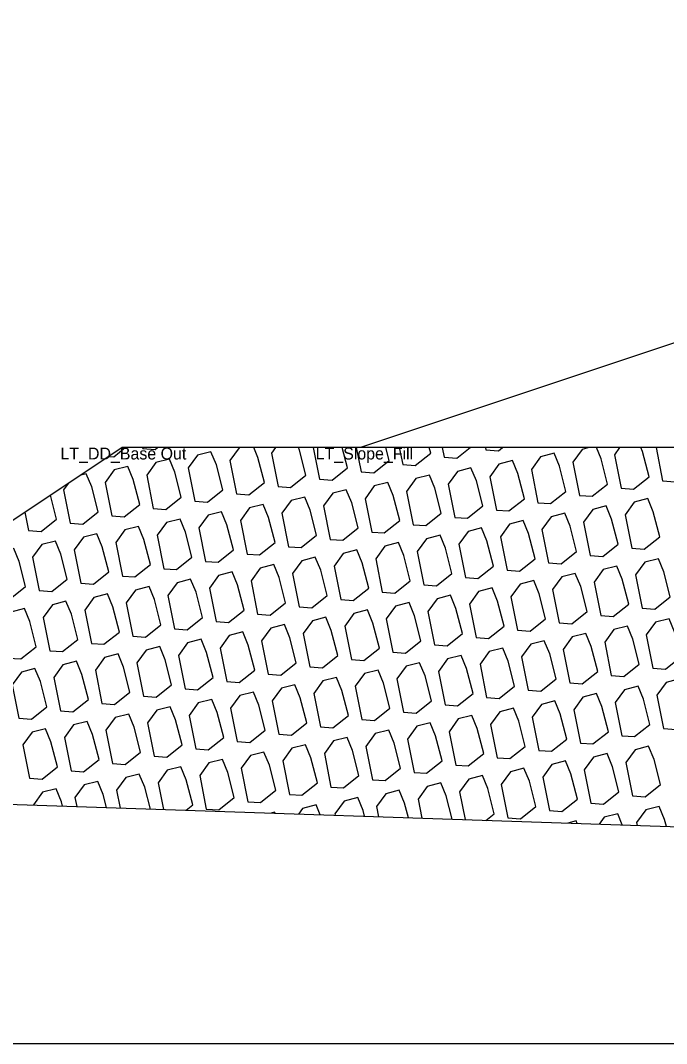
# Model space of a CAD drawing. Extents: x -26 to 203, y -10 to 20020.
# Drawn here: x 66.4 to 71.82, y 16000 to 16008.58 of the extents above; entities that cross this region are included whole.
import ezdxf

# ---------------------------------------------------------------- set-up
doc = ezdxf.new("R2010")
doc.units = 0
for name, color, linetype in [('Default', 7, 'Continuous'), ('Exist Cross Section Cell', 7, 'Continuous'), ('Exist XS Ground Line', 7, 'Continuous'), ('Old_Level_1', 7, 'Continuous'), ('Prop CMT Rip Rap Class II', 7, 'Continuous'), ('Prop CMT Slope Grass', 7, 'Continuous')]:
    doc.layers.add(name, color=color, linetype=linetype)

msp = doc.modelspace()

# ---------------------------------------------------------------- linework, layer by layer
at = {"layer": 'Exist Cross Section Cell'}
msp.add_line((0, 16000), (100, 16000), dxfattribs=at)
at = {"layer": 'Exist XS Ground Line'}
msp.add_line((50.1607, 16002.5529), (73.7016, 16001.7575), dxfattribs=at)
at = {"layer": 'Old_Level_1'}
for p, q in [((67.4213, 16005), (67.4229, 16004.992)), ((68.8532, 16005), (68.9061, 16004.7338)), ((69.2141, 16005), (69.2547, 16004.7952)), ((69.5749, 16005), (69.6033, 16004.8567)), ((69.9357, 16005), (69.9519, 16004.9182)), ((70.2965, 16005), (70.3005, 16004.9796)), ((71.7285, 16005), (71.7838, 16004.7214)), ((66.4354, 16004.4571), (66.4659, 16004.3035))]:
    msp.add_line(p, q, dxfattribs=at)
for points in [[(67.1385, 16004.9258), (67.1795, 16004.9228), (67.2764, 16005)], [(67.4229, 16004.992), (67.5281, 16004.9843), (67.5478, 16005)], [(68.241, 16005), (68.2304, 16004.9972), (68.1533, 16004.8908), (68.2089, 16004.6108)], [(68.2089, 16004.6108), (68.3142, 16004.6032), (68.4437, 16004.7064), (68.3893, 16004.917), (68.3551, 16005)], [(68.5365, 16005), (68.5019, 16004.9523), (68.5575, 16004.6723)], [(68.5575, 16004.6723), (68.6628, 16004.6646), (68.7923, 16004.7679), (68.7379, 16004.9784), (68.729, 16005)], [(68.9061, 16004.7338), (69.0114, 16004.7261), (69.1409, 16004.8293), (69.0968, 16005)], [(69.2547, 16004.7952), (69.36, 16004.7876), (69.4895, 16004.8908), (69.4613, 16005)], [(69.6033, 16004.8567), (69.7086, 16004.849), (69.8381, 16004.9523), (69.8258, 16005)], [(69.9519, 16004.9182), (70.0572, 16004.9105), (70.1695, 16005)], [(70.3005, 16004.9796), (70.4058, 16004.972), (70.4409, 16005)], [(71.1664, 16005), (71.108, 16004.9849), (71.031, 16004.8785), (71.0866, 16004.5985)], [(71.0866, 16004.5985), (71.1918, 16004.5908), (71.3214, 16004.6941), (71.2669, 16004.9046), (71.2277, 16005)], [(71.4231, 16005), (71.3796, 16004.94), (71.4352, 16004.66)], [(71.4352, 16004.66), (71.5404, 16004.6523), (71.67, 16004.7555), (71.6155, 16004.9661), (71.6016, 16005)], [(71.7838, 16004.7214), (71.889, 16004.7138), (72.0186, 16004.817), (71.9713, 16005)], [(66.8145, 16004.365), (66.9198, 16004.3573), (67.0493, 16004.4605), (66.9949, 16004.6711), (66.9498, 16004.7808), (66.9027, 16004.7686)], [(66.7979, 16004.6988), (66.7589, 16004.6449), (66.8145, 16004.365)], [(66.4659, 16004.3035), (66.5712, 16004.2958), (66.7008, 16004.3991), (66.6489, 16004.5995)], [(67.7867, 16001.9573), (67.8423, 16002.0016), (67.7879, 16002.2122), (67.7428, 16002.3219), (67.629, 16002.2925), (67.5519, 16002.1861), (67.5961, 16001.9638)], [(67.119, 16001.9799), (67.0907, 16002.0893), (67.0456, 16002.199), (66.9318, 16002.1696), (66.8547, 16002.0631), (66.8696, 16001.9883)], [(67.4867, 16001.9675), (67.4393, 16002.1508), (67.3942, 16002.2604), (67.2804, 16002.231), (67.2033, 16002.1246), (67.2328, 16001.976)], [(70.0188, 16001.8819), (69.9684, 16002.077), (69.9232, 16002.1866), (69.8095, 16002.1572), (69.7324, 16002.0508), (69.7642, 16001.8905)], [(70.3018, 16001.8724), (70.3714, 16001.9278), (70.317, 16002.1384), (70.2718, 16002.2481), (70.1581, 16002.2187), (70.081, 16002.1123), (70.1275, 16001.8782)], [(66.7513, 16001.9923), (66.7421, 16002.0278), (66.697, 16002.1375), (66.5832, 16002.1081), (66.5061, 16002.0017), (66.5064, 16002.0006)], [(69.6511, 16001.8943), (69.6198, 16002.0155), (69.5746, 16002.1252), (69.4609, 16002.0958), (69.3838, 16001.9893), (69.401, 16001.9028)], [(69.2834, 16001.9068), (69.2712, 16001.954), (69.226, 16002.0637), (69.1123, 16002.0343), (69.0352, 16001.9279), (69.0377, 16001.9151)], [(68.5324, 16001.9321), (68.5288, 16001.9408), (68.4997, 16001.9332)], [(68.9116, 16001.9193), (68.8774, 16002.0022), (68.7637, 16001.9728), (68.7294, 16001.9255)], [(71.4455, 16001.8337), (71.4065, 16001.9284), (71.2927, 16001.899), (71.2502, 16001.8403)], [(71.8155, 16001.8212), (71.8002, 16001.8802), (71.7551, 16001.9899), (71.6413, 16001.9605), (71.5643, 16001.8541), (71.5691, 16001.8295)], [(71.0663, 16001.8465), (71.0579, 16001.867), (70.9889, 16001.8491)]]:
    msp.add_lwpolyline(points, dxfattribs=at)
for points in [[(67.8603, 16004.5494), (67.9656, 16004.5417), (68.0951, 16004.6449), (68.0407, 16004.8555), (67.9955, 16004.9652), (67.8818, 16004.9358), (67.8047, 16004.8294)], [(70.738, 16004.537), (70.8433, 16004.5294), (70.9728, 16004.6326), (70.9183, 16004.8432), (70.8732, 16004.9529), (70.7594, 16004.9234), (70.6824, 16004.817)], [(67.1631, 16004.4264), (67.2684, 16004.4188), (67.3979, 16004.522), (67.3435, 16004.7326), (67.2984, 16004.8423), (67.1846, 16004.8128), (67.1075, 16004.7064)], [(67.5117, 16004.4879), (67.617, 16004.4802), (67.7465, 16004.5835), (67.6921, 16004.794), (67.647, 16004.9037), (67.5332, 16004.8743), (67.4561, 16004.7679)], [(70.3894, 16004.4756), (70.4947, 16004.4679), (70.6242, 16004.5711), (70.5697, 16004.7817), (70.5246, 16004.8914), (70.4108, 16004.862), (70.3338, 16004.7556)], [(69.6922, 16004.3526), (69.7975, 16004.345), (69.927, 16004.4482), (69.8726, 16004.6588), (69.8274, 16004.7685), (69.7137, 16004.739), (69.6366, 16004.6326)], [(70.0408, 16004.4141), (70.1461, 16004.4064), (70.2756, 16004.5097), (70.2212, 16004.7202), (70.176, 16004.8299), (70.0622, 16004.8005), (69.9852, 16004.6941)], [(69.3436, 16004.2912), (69.4489, 16004.2835), (69.5784, 16004.3867), (69.524, 16004.5973), (69.4788, 16004.707), (69.3651, 16004.6776), (69.288, 16004.5712)], [(68.6464, 16004.1682), (68.7517, 16004.1606), (68.8812, 16004.2638), (68.8268, 16004.4744), (68.7816, 16004.5841), (68.6679, 16004.5546), (68.5908, 16004.4482)], [(68.995, 16004.2297), (69.1003, 16004.222), (69.2298, 16004.3253), (69.1754, 16004.5358), (69.1302, 16004.6455), (69.0165, 16004.6161), (68.9394, 16004.5097)], [(68.2978, 16004.1068), (68.4031, 16004.0991), (68.5326, 16004.2023), (68.4782, 16004.4129), (68.433, 16004.5226), (68.3193, 16004.4932), (68.2422, 16004.3867)], [(71.1755, 16004.0944), (71.2807, 16004.0868), (71.4103, 16004.19), (71.3558, 16004.4006), (71.3107, 16004.5103), (71.1969, 16004.4808), (71.1199, 16004.3744)], [(71.5241, 16004.1559), (71.6293, 16004.1482), (71.7589, 16004.2515), (71.7044, 16004.462), (71.6593, 16004.5717), (71.5455, 16004.5423), (71.4685, 16004.4359)], [(67.9492, 16004.0453), (68.0545, 16004.0376), (68.184, 16004.1409), (68.1296, 16004.3514), (68.0844, 16004.4611), (67.9707, 16004.4317), (67.8936, 16004.3253)], [(70.8269, 16004.033), (70.9321, 16004.0253), (71.0617, 16004.1285), (71.0072, 16004.3391), (70.9621, 16004.4488), (70.8483, 16004.4194), (70.7713, 16004.3129)], [(67.252, 16003.9224), (67.3573, 16003.9147), (67.4868, 16004.0179), (67.4324, 16004.2285), (67.3872, 16004.3382), (67.2735, 16004.3088), (67.1964, 16004.2023)], [(67.6006, 16003.9838), (67.7059, 16003.9762), (67.8354, 16004.0794), (67.781, 16004.29), (67.7358, 16004.3997), (67.6221, 16004.3702), (67.545, 16004.2638)], [(70.1297, 16003.91), (70.2349, 16003.9024), (70.3645, 16004.0056), (70.31, 16004.2162), (70.2649, 16004.3259), (70.1511, 16004.2964), (70.0741, 16004.19)], [(70.4783, 16003.9715), (70.5835, 16003.9638), (70.7131, 16004.0671), (70.6586, 16004.2776), (70.6135, 16004.3873), (70.4997, 16004.3579), (70.4227, 16004.2515)], [(66.9034, 16003.8609), (67.0087, 16003.8532), (67.1382, 16003.9565), (67.0838, 16004.167), (67.0386, 16004.2767), (66.9249, 16004.2473), (66.8478, 16004.1409)], [(69.7811, 16003.8486), (69.8863, 16003.8409), (70.0159, 16003.9441), (69.9614, 16004.1547), (69.9163, 16004.2644), (69.8025, 16004.235), (69.7255, 16004.1285)], [(66.2062, 16003.738), (66.3115, 16003.7303), (66.441, 16003.8335), (66.3866, 16004.0441), (66.3414, 16004.1538), (66.2277, 16004.1244), (66.1506, 16004.0179)], [(66.5548, 16003.7994), (66.6601, 16003.7918), (66.7896, 16003.895), (66.7352, 16004.1056), (66.69, 16004.2153), (66.5763, 16004.1858), (66.4992, 16004.0794)], [(69.4325, 16003.7871), (69.5377, 16003.7794), (69.6673, 16003.8827), (69.6128, 16004.0932), (69.5677, 16004.2029), (69.4539, 16004.1735), (69.3769, 16004.0671)], [(68.7353, 16003.6642), (68.8406, 16003.6565), (68.9701, 16003.7597), (68.9156, 16003.9703), (68.8705, 16004.08), (68.7567, 16004.0506), (68.6797, 16003.9441)], [(69.0839, 16003.7256), (69.1892, 16003.718), (69.3187, 16003.8212), (69.2642, 16004.0318), (69.2191, 16004.1415), (69.1053, 16004.112), (69.0283, 16004.0056)], [(71.6129, 16003.6518), (71.7182, 16003.6442), (71.8477, 16003.7474), (71.7933, 16003.958), (71.7482, 16004.0677), (71.6344, 16004.0382), (71.5573, 16003.9318)], [(68.3867, 16003.6027), (68.492, 16003.595), (68.6215, 16003.6983), (68.5671, 16003.9088), (68.5219, 16004.0185), (68.4081, 16003.9891), (68.3311, 16003.8827)], [(71.2643, 16003.5904), (71.3696, 16003.5827), (71.4991, 16003.6859), (71.4447, 16003.8965), (71.3996, 16004.0062), (71.2858, 16003.9768), (71.2087, 16003.8703)], [(67.6895, 16003.4798), (67.7948, 16003.4721), (67.9243, 16003.5753), (67.8699, 16003.7859), (67.8247, 16003.8956), (67.711, 16003.8662), (67.6339, 16003.7597)], [(68.0381, 16003.5412), (68.1434, 16003.5336), (68.2729, 16003.6368), (68.2185, 16003.8474), (68.1733, 16003.9571), (68.0595, 16003.9276), (67.9825, 16003.8212)], [(70.9158, 16003.5289), (71.021, 16003.5212), (71.1506, 16003.6245), (71.0961, 16003.835), (71.051, 16003.9447), (70.9372, 16003.9153), (70.8601, 16003.8089)], [(67.3409, 16003.4183), (67.4462, 16003.4106), (67.5757, 16003.5139), (67.5213, 16003.7244), (67.4761, 16003.8341), (67.3624, 16003.8047), (67.2853, 16003.6983)], [(70.2186, 16003.406), (70.3238, 16003.3983), (70.4534, 16003.5015), (70.3989, 16003.7121), (70.3538, 16003.8218), (70.24, 16003.7924), (70.1629, 16003.6859)], [(70.5672, 16003.4674), (70.6724, 16003.4598), (70.802, 16003.563), (70.7475, 16003.7736), (70.7024, 16003.8833), (70.5886, 16003.8538), (70.5115, 16003.7474)], [(66.9923, 16003.3568), (67.0976, 16003.3492), (67.2271, 16003.4524), (67.1727, 16003.663), (67.1275, 16003.7727), (67.0138, 16003.7432), (66.9367, 16003.6368)], [(69.87, 16003.3445), (69.9752, 16003.3368), (70.1048, 16003.4401), (70.0503, 16003.6506), (70.0052, 16003.7603), (69.8914, 16003.7309), (69.8144, 16003.6245)], [(66.2951, 16003.2339), (66.4004, 16003.2262), (66.5299, 16003.3295), (66.4755, 16003.54), (66.4303, 16003.6497), (66.3166, 16003.6203), (66.2395, 16003.5139)], [(66.6437, 16003.2954), (66.749, 16003.2877), (66.8785, 16003.3909), (66.8241, 16003.6015), (66.7789, 16003.7112), (66.6652, 16003.6818), (66.5881, 16003.5753)], [(69.1728, 16003.2216), (69.278, 16003.2139), (69.4076, 16003.3171), (69.3531, 16003.5277), (69.308, 16003.6374), (69.1942, 16003.608), (69.1172, 16003.5015)], [(69.5214, 16003.283), (69.6266, 16003.2754), (69.7562, 16003.3786), (69.7017, 16003.5892), (69.6566, 16003.6989), (69.5428, 16003.6694), (69.4658, 16003.563)], [(68.8242, 16003.1601), (68.9294, 16003.1524), (69.059, 16003.2557), (69.0045, 16003.4662), (68.9594, 16003.5759), (68.8456, 16003.5465), (68.7686, 16003.4401)], [(71.7018, 16003.1478), (71.8071, 16003.1401), (71.9366, 16003.2433), (71.8822, 16003.4539), (71.837, 16003.5636), (71.7233, 16003.5342), (71.6462, 16003.4277)], [(68.4756, 16003.0986), (68.5808, 16003.091), (68.7104, 16003.1942), (68.6559, 16003.4048), (68.6108, 16003.5145), (68.497, 16003.485), (68.42, 16003.3786)], [(71.3532, 16003.0863), (71.4585, 16003.0786), (71.588, 16003.1819), (71.5336, 16003.3924), (71.4884, 16003.5021), (71.3747, 16003.4727), (71.2976, 16003.3663)], [(67.7784, 16002.9757), (67.8836, 16002.968), (68.0132, 16003.0713), (67.9587, 16003.2818), (67.9136, 16003.3915), (67.7998, 16003.3621), (67.7228, 16003.2557)], [(68.127, 16003.0372), (68.2322, 16003.0295), (68.3618, 16003.1327), (68.3073, 16003.3433), (68.2622, 16003.453), (68.1484, 16003.4236), (68.0714, 16003.3171)], [(71.0046, 16003.0248), (71.1099, 16003.0172), (71.2394, 16003.1204), (71.185, 16003.331), (71.1398, 16003.4407), (71.0261, 16003.4112), (70.949, 16003.3048)], [(67.4298, 16002.9142), (67.535, 16002.9066), (67.6646, 16003.0098), (67.6101, 16003.2204), (67.565, 16003.3301), (67.4512, 16003.3006), (67.3742, 16003.1942)], [(70.3074, 16002.9019), (70.4127, 16002.8942), (70.5422, 16002.9975), (70.4878, 16003.208), (70.4427, 16003.3177), (70.3289, 16003.2883), (70.2518, 16003.1819)], [(70.656, 16002.9634), (70.7613, 16002.9557), (70.8908, 16003.0589), (70.8364, 16003.2695), (70.7912, 16003.3792), (70.6775, 16003.3498), (70.6004, 16003.2433)], [(67.0812, 16002.8527), (67.1865, 16002.8451), (67.316, 16002.9483), (67.2615, 16003.1589), (67.2164, 16003.2686), (67.1026, 16003.2392), (67.0256, 16003.1327)], [(69.9588, 16002.8404), (70.0641, 16002.8328), (70.1936, 16002.936), (70.1392, 16003.1466), (70.0941, 16003.2563), (69.9803, 16003.2268), (69.9032, 16003.1204)], [(66.384, 16002.7298), (66.4893, 16002.7222), (66.6188, 16002.8254), (66.5644, 16003.036), (66.5192, 16003.1457), (66.4054, 16003.1162), (66.3284, 16003.0098)], [(66.7326, 16002.7913), (66.8379, 16002.7836), (66.9674, 16002.8869), (66.9129, 16003.0974), (66.8678, 16003.2071), (66.754, 16003.1777), (66.677, 16003.0713)], [(69.2616, 16002.7175), (69.3669, 16002.7098), (69.4965, 16002.8131), (69.442, 16003.0236), (69.3969, 16003.1333), (69.2831, 16003.1039), (69.206, 16002.9975)], [(69.6102, 16002.7789), (69.7155, 16002.7713), (69.845, 16002.8745), (69.7906, 16003.0851), (69.7455, 16003.1948), (69.6317, 16003.1654), (69.5546, 16003.0589)], [(68.9131, 16002.656), (69.0183, 16002.6484), (69.1479, 16002.7516), (69.0934, 16002.9622), (69.0483, 16003.0719), (68.9345, 16003.0424), (68.8574, 16002.936)], [(71.7907, 16002.6437), (71.896, 16002.636), (72.0255, 16002.7393), (71.9711, 16002.9498), (71.9259, 16003.0595), (71.8122, 16003.0301), (71.7351, 16002.9237)], [(68.5645, 16002.5945), (68.6697, 16002.5869), (68.7993, 16002.6901), (68.7448, 16002.9007), (68.6997, 16003.0104), (68.5859, 16002.981), (68.5088, 16002.8745)], [(71.4421, 16002.5822), (71.5474, 16002.5746), (71.6769, 16002.6778), (71.6225, 16002.8884), (71.5773, 16002.9981), (71.4636, 16002.9686), (71.3865, 16002.8622)], [(67.8673, 16002.4716), (67.9725, 16002.464), (68.1021, 16002.5672), (68.0476, 16002.7778), (68.0025, 16002.8874), (67.8887, 16002.858), (67.8117, 16002.7516)], [(68.2159, 16002.5331), (68.3211, 16002.5254), (68.4507, 16002.6287), (68.3962, 16002.8392), (68.3511, 16002.9489), (68.2373, 16002.9195), (68.1602, 16002.8131)], [(70.7449, 16002.4593), (70.8502, 16002.4516), (70.9797, 16002.5549), (70.9253, 16002.7654), (70.8801, 16002.8751), (70.7664, 16002.8457), (70.6893, 16002.7393)], [(71.0935, 16002.5207), (71.1988, 16002.5131), (71.3283, 16002.6163), (71.2739, 16002.8269), (71.2287, 16002.9366), (71.115, 16002.9072), (71.0379, 16002.8007)], [(67.5187, 16002.4101), (67.6239, 16002.4025), (67.7535, 16002.5057), (67.699, 16002.7163), (67.6539, 16002.826), (67.5401, 16002.7966), (67.4631, 16002.6901)], [(70.3963, 16002.3978), (70.5016, 16002.3902), (70.6311, 16002.4934), (70.5767, 16002.704), (70.5315, 16002.8136), (70.4178, 16002.7842), (70.3407, 16002.6778)], [(66.8215, 16002.2872), (66.9267, 16002.2796), (67.0563, 16002.3828), (67.0018, 16002.5934), (66.9567, 16002.703), (66.8429, 16002.6736), (66.7659, 16002.5672)], [(67.1701, 16002.3487), (67.2753, 16002.341), (67.4049, 16002.4442), (67.3504, 16002.6548), (67.3053, 16002.7645), (67.1915, 16002.7351), (67.1145, 16002.6287)], [(70.0477, 16002.3363), (70.153, 16002.3287), (70.2825, 16002.4319), (70.2281, 16002.6425), (70.1829, 16002.7522), (70.0692, 16002.7228), (69.9921, 16002.6163)], [(66.4729, 16002.2257), (66.5781, 16002.2181), (66.7077, 16002.3213), (66.6532, 16002.5319), (66.6081, 16002.6416), (66.4943, 16002.6122), (66.4173, 16002.5057)], [(69.3505, 16002.2134), (69.4558, 16002.2058), (69.5853, 16002.309), (69.5309, 16002.5196), (69.4857, 16002.6292), (69.372, 16002.5998), (69.2949, 16002.4934)], [(69.6991, 16002.2749), (69.8044, 16002.2672), (69.9339, 16002.3704), (69.8795, 16002.581), (69.8343, 16002.6907), (69.7206, 16002.6613), (69.6435, 16002.5549)], [(69.0019, 16002.1519), (69.1072, 16002.1443), (69.2367, 16002.2475), (69.1823, 16002.4581), (69.1371, 16002.5678), (69.0234, 16002.5384), (68.9463, 16002.4319)], [(68.3047, 16002.029), (68.41, 16002.0214), (68.5395, 16002.1246), (68.4851, 16002.3352), (68.44, 16002.4448), (68.3262, 16002.4154), (68.2491, 16002.309)], [(68.6533, 16002.0905), (68.7586, 16002.0828), (68.8881, 16002.186), (68.8337, 16002.3966), (68.7885, 16002.5063), (68.6748, 16002.4769), (68.5977, 16002.3705)], [(71.531, 16002.0781), (71.6363, 16002.0705), (71.7658, 16002.1737), (71.7113, 16002.3843), (71.6662, 16002.494), (71.5524, 16002.4646), (71.4754, 16002.3581)], [(67.9561, 16001.9675), (68.0614, 16001.9599), (68.1909, 16002.0631), (68.1365, 16002.2737), (68.0914, 16002.3834), (67.9776, 16002.354), (67.9005, 16002.2475)], [(70.8338, 16001.9552), (70.9391, 16001.9476), (71.0686, 16002.0508), (71.0142, 16002.2614), (70.969, 16002.371), (70.8552, 16002.3416), (70.7782, 16002.2352)], [(71.1824, 16002.0167), (71.2877, 16002.009), (71.4172, 16002.1122), (71.3628, 16002.3228), (71.3176, 16002.4325), (71.2038, 16002.4031), (71.1268, 16002.2967)], [(70.4852, 16001.8937), (70.5905, 16001.8861), (70.72, 16001.9893), (70.6656, 16002.1999), (70.6204, 16002.3096), (70.5067, 16002.2802), (70.4296, 16002.1737)]]:
    msp.add_lwpolyline(points, close=True, dxfattribs=at)
at = {"layer": 'Prop CMT Rip Rap Class II'}
msp.add_lwpolyline([(76.3889, 16005), (67.2497, 16005), (62.932, 16002.1214)], dxfattribs=at)
at = {"layer": 'Prop CMT Slope Grass'}
msp.add_lwpolyline([(80, 16008.5831), (69.2496, 16005)], dxfattribs=at)

# ---------------------------------------------------------------- texts
at = {"layer": 'Default'}
for s, p in [('LT_DD_Base Out', (66.7331, 16004.9)), ('LT_Slope_Fill', (68.8734, 16004.9))]:
    msp.add_text(s, height=0.1, dxfattribs=at).set_placement(p)

doc.saveas('drawing.dxf')
